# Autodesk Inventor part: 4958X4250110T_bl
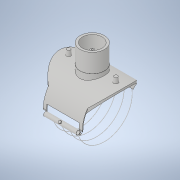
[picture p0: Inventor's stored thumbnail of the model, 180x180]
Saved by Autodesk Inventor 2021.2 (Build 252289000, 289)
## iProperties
Created: 2020-06
Part Number: 4958X4250110T_bl
Material: Generic
Description: Plasson Branch Saddle 250x110
Document SubType Name: Modeling
Designer: KIM
Density: 1 g/cm^3
Appearance: Default
Author: KIM
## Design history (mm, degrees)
derived "4958X4.ipt"
feature "Solid1::4958X4.ipt" dims "ScaleForDerivedMember" = 10
tag "TaggingFeature1"
body "Solid1"
other parameters: "d0" = 295 [user parameter], "d3" = 268 [user parameter], "d4" = 111 [user parameter], "d7" = 89 [user parameter], "d9" = 84 [user parameter], "d10" = 0.5 [user parameter], "d11" = 1 [user parameter], "d12" = 27.75 [user parameter], "d13" = 16 [user parameter], "d14" = 8 [user parameter], "d16" = 10 deg [user parameter], "d17" = 10 deg [user parameter], "d19" = 0 [user parameter], "d23" = 0 [user parameter], "d26" = 0 [user parameter], "d27" = 177 [user parameter], "d28" = 0 [user parameter], "d29" = 147.5 [user parameter], "d30" = 0 [user parameter], "d31" = 1 [user parameter], "d32" = 1 [user parameter], "d33" = 19.2 [user parameter], "d34" = 9.6 [user parameter], "d35" = 45 deg [user parameter], "d36" = 147.5 [user parameter], "d37" = 0 [user parameter], "d38" = 5 [user parameter], "d39" = 85 deg [user parameter], "d40" = 27.75 [user parameter], "d41" = 16 [user parameter], "d42" = 107.27273 [user parameter], "d49" = 3 [user parameter], "d50" = 6 [user parameter], "d51" = 5 [user parameter], "d54" = 0 [user parameter], "d57" = 35 deg [user parameter], "d60" = 18.4375 [user parameter], "d61" = 1 [user parameter], "d62" = 90 deg [user parameter], "d63" = 2 [user parameter], "d64" = 0 [user parameter], "d65" = 0 [user parameter], "d68" = 36.875 [user parameter], "d70" = 0.57711 [user parameter], "d71" = 10 deg [user parameter], "d73" = 3.15 [user parameter], "L" = 295 [user parameter], "LS" = 84 [user parameter], "H1" = 111 [user parameter], "Dt" = 16 [user parameter], "di" = 89 [user parameter], "d72" = 9 [user parameter]
